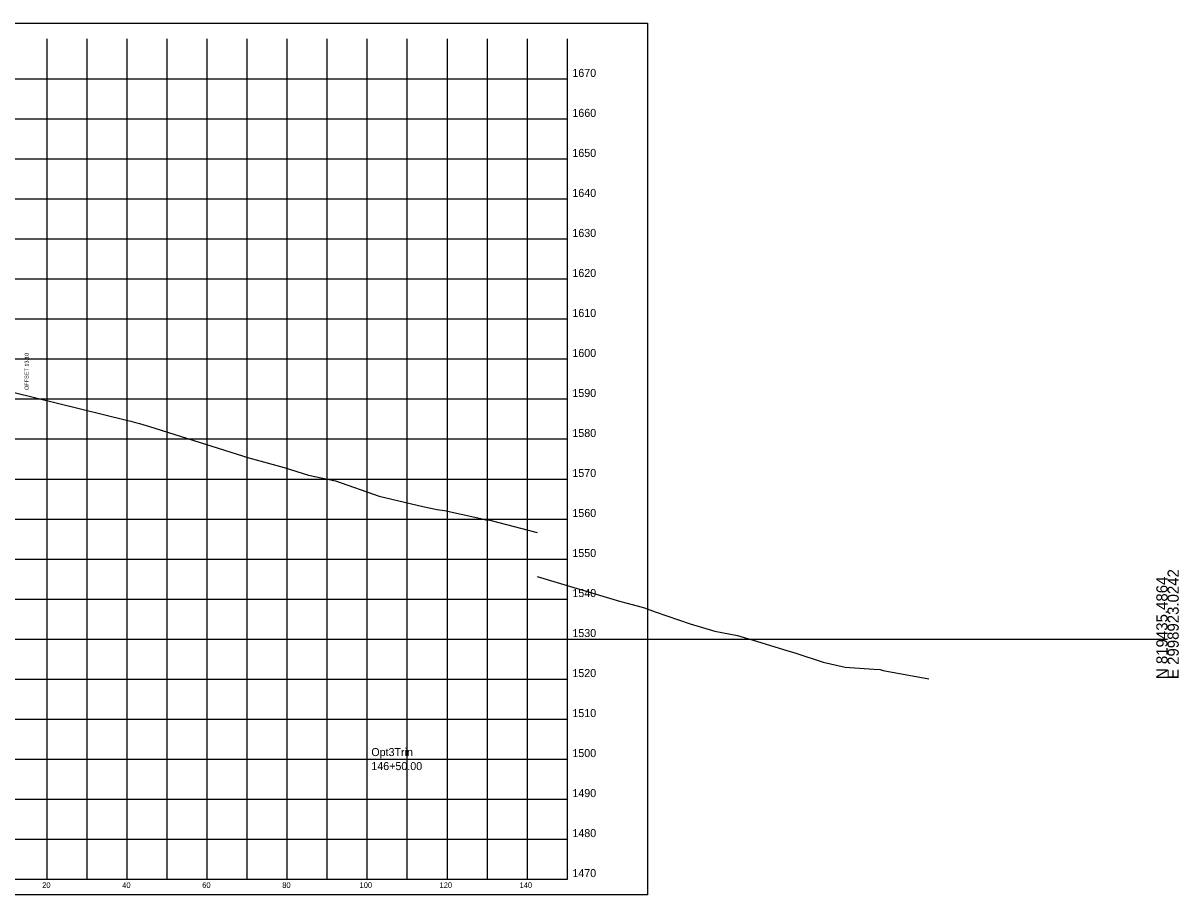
# Model space of a CAD drawing. Extents: x -26 to 603, y -10 to 4805.
# Drawn here: x 314 to 602.8, y 947.1 to 1164.9 of the extents above; entities that cross this region are included whole.
import ezdxf

# ---------------------------------------------------------------- set-up
doc = ezdxf.new("R2010")
doc.units = 0
for name, color, linetype in [('DESIGN - SHEET - Corner Text', 7, 'Continuous'), ('DESIGN - SHEET - Light Grid', 7, 'Continuous'), ('DESIGN - SHEET - Linework', 7, 'Continuous'), ('DESIGN - SHEET - Plot Shape', 7, 'Continuous'), ('DESIGN - TYPICAL - Slope Tie Text', 7, 'Continuous'), ('DESIGN - TYPICAL - Warning Text', 7, 'Continuous'), ('SURVEY - GROUND - Top of Ground', 7, 'Continuous')]:
    doc.layers.add(name, color=color, linetype=linetype)

msp = doc.modelspace()

# ---------------------------------------------------------------- linework, layer by layer
at = {"layer": 'DESIGN - SHEET - Light Grid'}
msp.add_line((300, 1011), (600, 1011), dxfattribs=at)
at = {"layer": 'DESIGN - SHEET - Linework'}
for p, q in [((320, 951), (320, 1161)), ((330, 951), (330, 1161)), ((340, 951), (340, 1161)), ((350, 951), (350, 1161)), ((360, 951), (360, 1161)), ((370, 951), (370, 1161)), ((380, 951), (380, 1161)), ((390, 951), (390, 1161)), ((400, 951), (400, 1161)), ((410, 951), (410, 1161)), ((420, 951), (420, 1161)), ((430, 951), (430, 1161)), ((440, 951), (440, 1161)), ((150, 1151), (450, 1151)), ((150, 1141), (450, 1141)), ((150, 1131), (450, 1131)), ((150, 1121), (450, 1121)), ((150, 1111), (450, 1111)), ((150, 1101), (450, 1101)), ((150, 1091), (450, 1091)), ((150, 1081), (450, 1081)), ((150, 1071), (450, 1071)), ((150, 1061), (450, 1061)), ((150, 1051), (450, 1051)), ((150, 1041), (450, 1041)), ((150, 1031), (450, 1031)), ((150, 1021), (450, 1021)), ((150, 1011), (450, 1011)), ((150, 1001), (450, 1001)), ((150, 991), (450, 991)), ((150, 981), (450, 981)), ((150, 971), (450, 971)), ((150, 961), (450, 961))]:
    msp.add_line(p, q, dxfattribs=at)
msp.add_lwpolyline([(150, 1161), (150, 951), (450, 951), (450, 1161)], dxfattribs=at)
at = {"layer": 'DESIGN - SHEET - Plot Shape'}
msp.add_lwpolyline([(130, 1164.94), (470, 1164.94), (470, 947.06), (130, 947.06)], close=True, dxfattribs=at)
at = {"layer": 'SURVEY - GROUND - Top of Ground'}
msp.add_line((442.44, 1026.61), (463.05, 1020.47), dxfattribs=at)
for points in [[(311.38, 1072.73), (339.81, 1065.68), (340.91, 1065.44), (342.08, 1065.16), (343.02, 1064.88), (345.54, 1064.12), (370.41, 1056.26), (379.18, 1053.84), (385.32, 1051.93), (392.08, 1050.54), (403, 1046.74), (413.84, 1044.15), (417.42, 1043.39), (419.33, 1043.1), (427.58, 1041.31), (429.61, 1040.81), (430.58, 1040.71), (442.44, 1037.61)], [(463.05, 1020.47), (464.95, 1019.94), (468.37, 1019.05), (469.28, 1018.79), (471.96, 1017.82), (480.65, 1014.83), (486.84, 1013), (492.48, 1011.85), (497.3, 1010.45), (504.02, 1008.35), (507.08, 1007.48), (513.91, 1005.24), (519.46, 1004.01), (526.61, 1003.46), (528.14, 1003.36), (528.9, 1003.15), (540.33, 1001.03)]]:
    msp.add_lwpolyline(points, dxfattribs=at)

# ---------------------------------------------------------------- texts
at = {"layer": 'DESIGN - SHEET - Corner Text'}
for s, height, p in [('1670', 2, (451.25, 1151.5)), ('1660', 2, (451.25, 1141.5)), ('1650', 2, (451.25, 1131.5)), ('1640', 2, (451.25, 1121.5)), ('1630', 2, (451.25, 1111.5)), ('1620', 2, (451.25, 1101.5)), ('1610', 2, (451.25, 1091.5)), ('1600', 2, (451.25, 1081.5)), ('1590', 2, (451.25, 1071.5)), ('1580', 2, (451.25, 1061.5)), ('1570', 2, (451.25, 1051.5)), ('1560', 2, (451.25, 1041.5)), ('1550', 2, (451.25, 1031.5)), ('1540', 2, (451.25, 1021.5)), ('1530', 2, (451.25, 1011.5)), ('1520', 2, (451.25, 1001.5)), ('1510', 2, (451.25, 991.5)), ('1500', 2, (451.25, 981.5)), ('1490', 2, (451.25, 971.5)), ('1480', 2, (451.25, 961.5)), ('1470', 2, (451.25, 951.5)), ('20', 1.4, (318.74, 948.8)), ('40', 1.4, (338.74, 948.8)), ('60', 1.4, (358.74, 948.8)), ('80', 1.4, (378.74, 948.8)), ('100', 1.4, (398.06, 948.8)), ('120', 1.4, (418.06, 948.8)), ('140', 1.4, (438.06, 948.8))]:
    msp.add_text(s, height=height, dxfattribs=at).set_placement(p)
at = {"layer": 'DESIGN - SHEET - Light Grid'}
for s, p in [('N 819435.4864', (600, 1001)), ('E 2998923.0242', (602.8, 1001))]:
    msp.add_text(s, height=2.8, rotation=90, dxfattribs=at).set_placement(p)
at = {"layer": 'DESIGN - TYPICAL - Slope Tie Text'}
msp.add_text('OFFSET 13.10', height=1, rotation=90, dxfattribs=at).set_placement((315.35, 1073.25))
at = {"layer": 'DESIGN - TYPICAL - Warning Text'}
for s, p in [('Opt3Trin', (401, 981.75)), ('146+50.00', (401, 978.25))]:
    msp.add_text(s, height=2, dxfattribs=at).set_placement(p)

doc.saveas('drawing.dxf')
